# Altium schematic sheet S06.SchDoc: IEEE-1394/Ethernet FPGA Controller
size 381 x 254 mm; Revision: 3.2; SheetNumber: 6; SheetTotal: 10
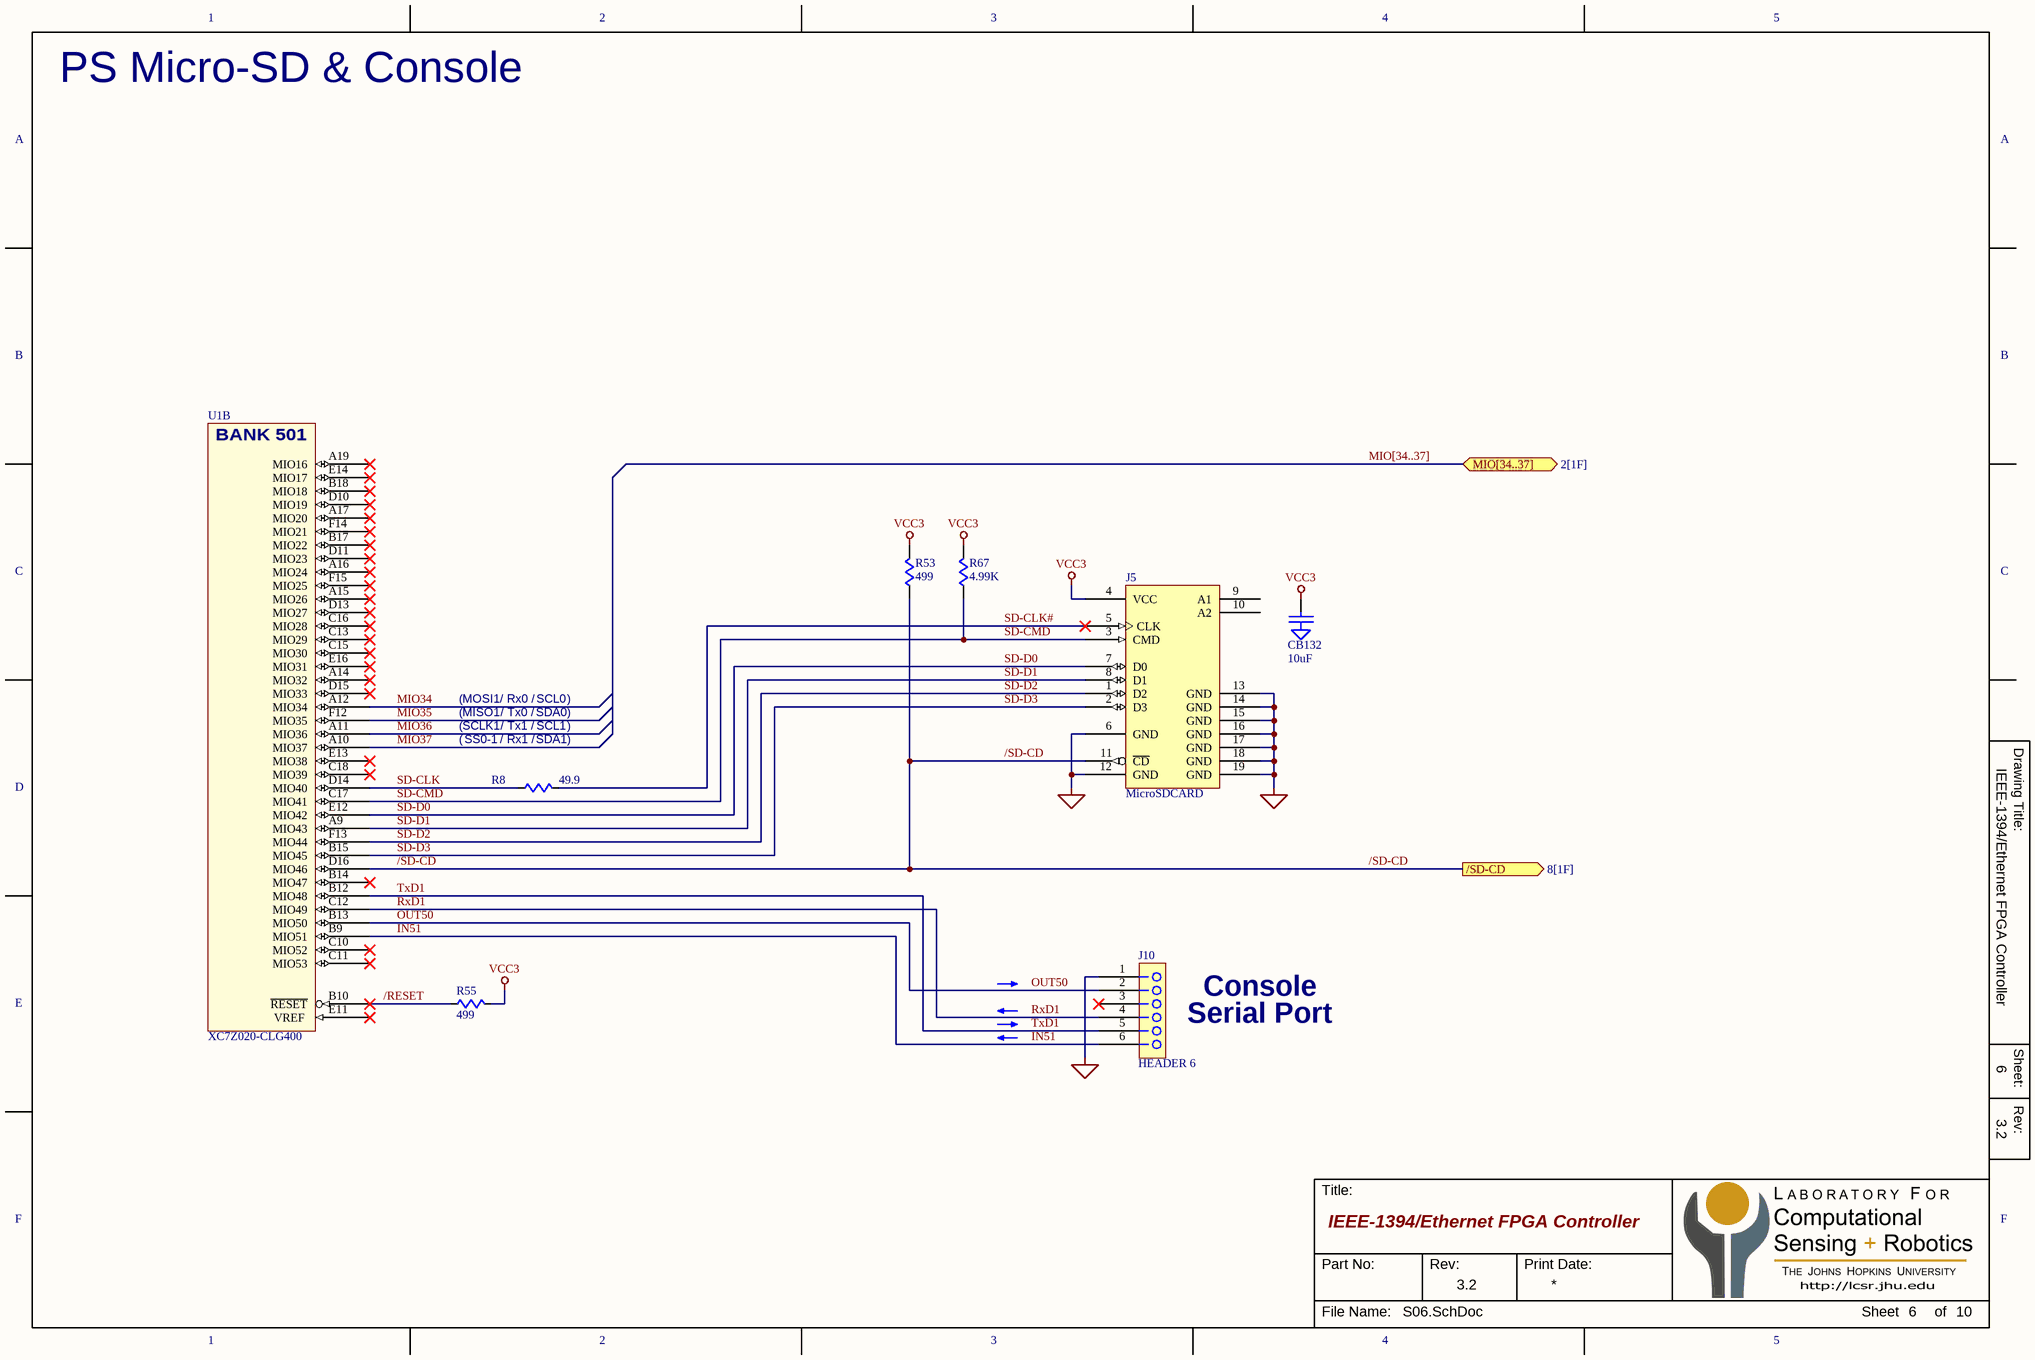
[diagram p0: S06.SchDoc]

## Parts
CB132  10uF  [CB0603]
J5  MicroSDCARD  [CONN-uSD-JAE-ST12S0]
J10  HEADER 6  [HDR-6x1-100]
R8  49.9  [R0201]
R53  499  [R0402]
R55  499  [R0402]
R67  4.99K  [R0402]
U1  XC7Z020-CLG400  [BGA-400-08mm]  (part B of 9)

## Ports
/SD-CD (out, see 8[1F]), MIO[34..37] (bidir, see 2[1F])

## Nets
GND: CB132.2(GND) J5.6(GND) J5.12(GND) J5.13(GND) J5.14(GND) J5.15(GND) J5.16(GND) J5.17(GND) J5.18(GND) J5.19(GND) J10.1
VCC3: CB132.1 J5.4(VCC) R53.2 R55.2 R67.2
/RESET: R55.1 U1.B10(~{RESET})
/SD-CD: J5.11(~{CD}) R53.1 U1.D16(MIO46) ; port /SD-CD
IN51: J10.6 U1.B9(MIO51)
MIO34: U1.A12(MIO34)
MIO35: U1.F12(MIO35)
MIO36: U1.A11(MIO36)
MIO37: U1.A10(MIO37)
OUT50: J10.2 U1.B13(MIO50)
RxD1: J10.4 U1.C12(MIO49)
SD-CLK: R8.1 U1.D14(MIO40)
SD-CLK#: J5.5(CLK) R8.2
SD-CMD: J5.3(CMD) R67.1 U1.C17(MIO41)
SD-D0: J5.7(D0) U1.E12(MIO42)
SD-D1: J5.8(D1) U1.A9(MIO43)
SD-D2: J5.1(D2) U1.F13(MIO44)
SD-D3: J5.2(D3) U1.B15(MIO45)
TxD1: J10.5 U1.B12(MIO48)

Not connected (* = marked no-connect by the designer): J5 9(A1) 10(A2); J10 3*; U1 A14(MIO32)* A15(MIO26)* A16(MIO24)* A17(MIO20)* A19(MIO16)* B14(MIO47)* B17(MIO22)* B18(MIO18)* C10(MIO52)* C11(MIO53)* C13(MIO29)* C15(MIO30)* C16(MIO28)* C18(MIO39)* D10(MIO19)* D11(MIO23)* D13(MIO27)* D15(MIO33)* E11(VREF_)* E13(MIO38)* E14(MIO17)* E16(MIO31)* F14(MIO21)* F15(MIO25)*

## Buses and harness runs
bus MIO[34..37] = port MIO[34..37]

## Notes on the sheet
- PS Micro-SD & Console
- (
- MOSI1
- / Rx0 /
- SCL0
- )
- MISO1
- SCLK1
- (near R8) SS0-1
- / Tx0 /
- / Tx1 /
- (near R8) / Rx1 /
- SDA0
- SCL1
- (near R8) SDA1
- (near R8) )
- Console
- (near J10) Serial Port

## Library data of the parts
CB132 = CAP-GND
J5 = CONN-MICROSD-ST12S0
R8 R53 R55 R67 = R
